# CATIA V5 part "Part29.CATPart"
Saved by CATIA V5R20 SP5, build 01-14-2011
Part number: Part29
Material "Water": density 1000 kg/m3
Bounding box of the stored display mesh (mm): x -1.919 to 1.919, y -2 to 2, z -1.919 to 1.919
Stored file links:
  D:\新建文件夹\Part29.CATPart
  C:\Program Files\Dassault Systemes\B20\intel_a\startup\materials\Catalog.CATMaterial
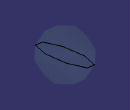
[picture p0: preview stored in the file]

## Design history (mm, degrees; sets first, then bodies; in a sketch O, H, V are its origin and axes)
Body1 (main body), material "Water"
  Sketch1 on xy-plane, origin (0, 0, 0), H (1, 0, 0), V (0, 1, 0)
    arc A1 centre (0, 0) radius 2 from (0, -2) to (0, 2) ccw
    axis line L1 (0, 2.6954) -> (0, -2.923)
    point P1 (0, 2.6954)
    point P3 (0, 2)
    point P4 (0, -2)
    radius A1 = 2
    coincidence: P1 V, L1 P3, L1 P4
    vertical: L1 V
  Shaft1: profile Sketch1, axis Sketch1.L1, angle 360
